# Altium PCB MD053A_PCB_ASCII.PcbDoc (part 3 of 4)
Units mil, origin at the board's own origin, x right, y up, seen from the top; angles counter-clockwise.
Board outline 3650 x 5180 mil, 4 copper layers (Top Layer, GND Layer, Power Layer, Bottom Layer), stack 58.4 mil thick; 251 components, 138 nets, 532 pads, 1017 vias.
Unrouted connection lines stored in the file: 42.
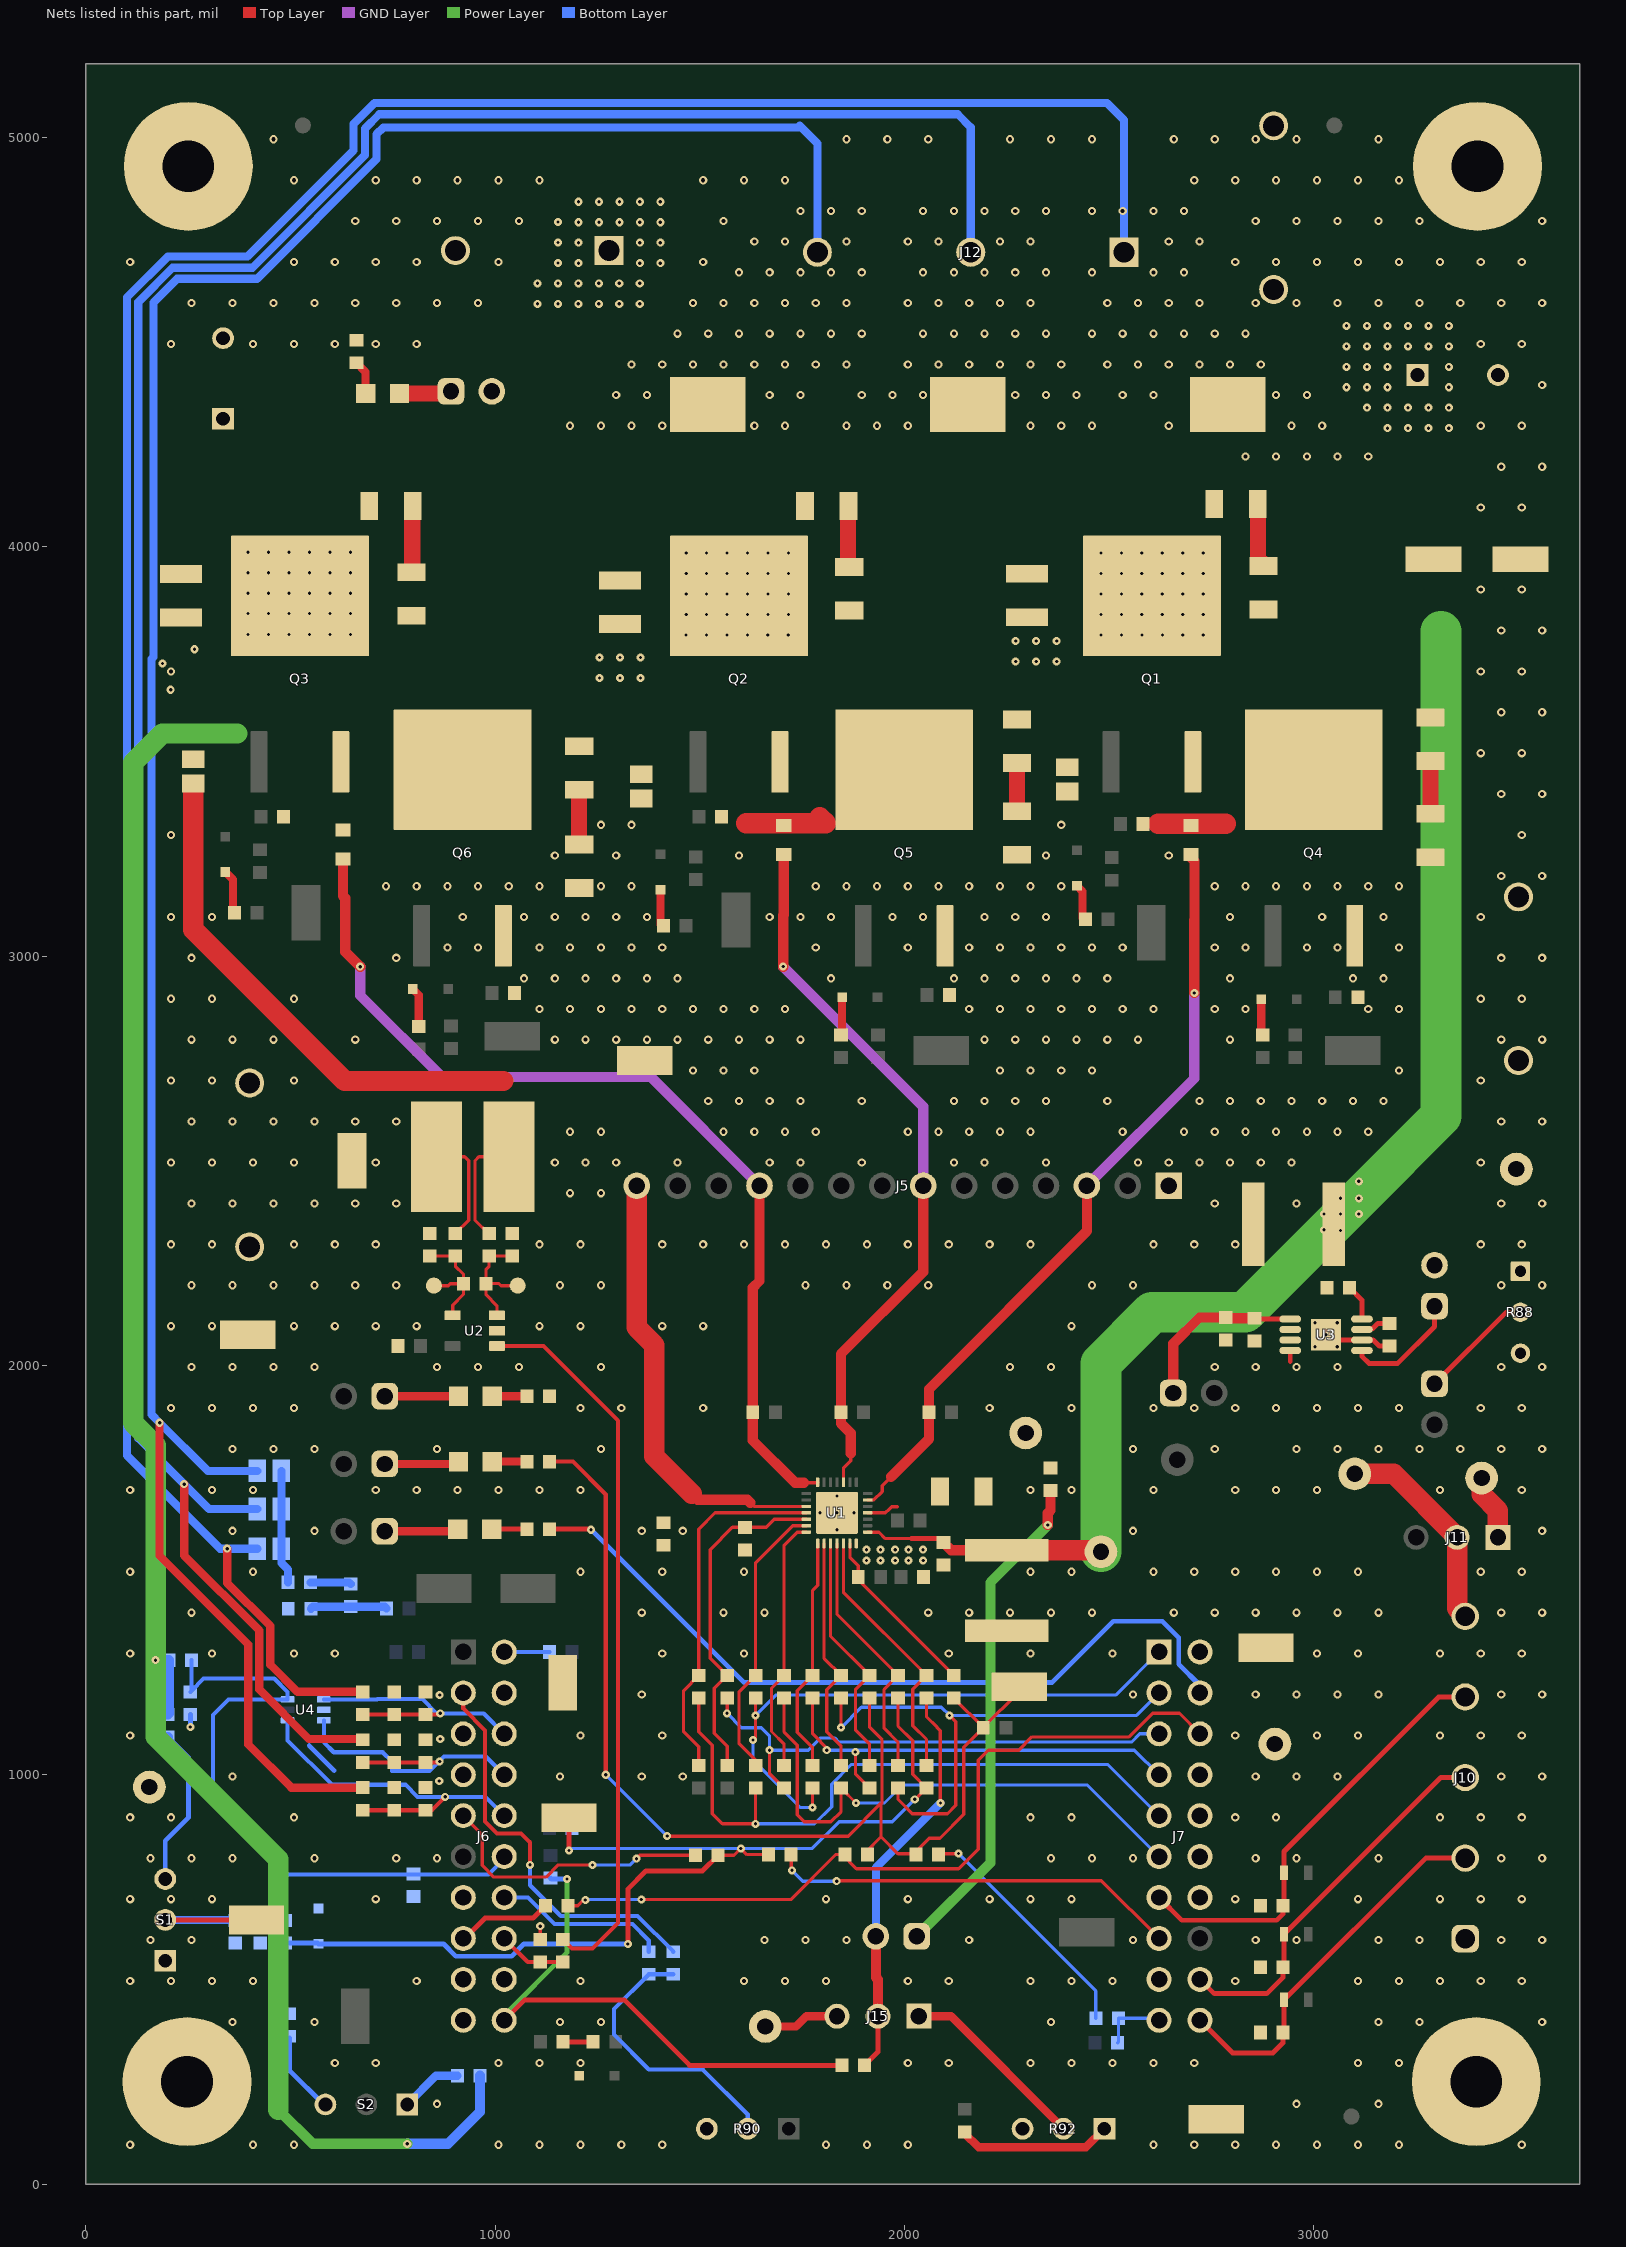
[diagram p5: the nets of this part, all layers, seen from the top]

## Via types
v1: diameter 20, hole 10, Top Layer to Bottom Layer, tented both sides, 759 vias
v2: diameter 19.68, hole 7.87, Top Layer to Bottom Layer, tented both sides, 248 vias
v3: diameter 19.68, hole 7.87, Top Layer to Bottom Layer, 10 vias

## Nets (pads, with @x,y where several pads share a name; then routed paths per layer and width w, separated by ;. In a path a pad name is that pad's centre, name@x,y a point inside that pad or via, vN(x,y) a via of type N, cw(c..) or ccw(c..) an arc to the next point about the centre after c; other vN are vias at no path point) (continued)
GND: C1.1 C2.2 C4.2 C5.2 C7.2 C14.2 C16.2 C18.2 C28.1 C29.2 C31.2 C32.2 C33.2 C34.2 C35.2 C36.2 C37.2 C38.2 C39.2 C40.2 C41.2 C42.2 C43.2 C44.2 C45.1 C46.2 C47.2 C48.2 D11.2 D12.2 J5.1 J6.4 J7.2 J9.2 J10.1 R22.1 R24.1 R60.1 R61.2 R66.1 R70.1 R71.1 R72.1 R77.1 R80.1 R86.1 R88.1 R90.3 R91.1 R92.3 TP5.1 TP6.1 TP7.1 TP9.1 TP10.1 TP22.1 TP25.1 TP25.2 TP26.1 TP26.2 TP27.1 TP27.2 TP28.1 TP29.1 U1.28 U1.29 U2.2 U3.4 U3.6 U3.9 U4.2 | length 616
  Top Layer w7.87: R60.1@856.42,2510 925,2510 935,2500 935,2354.96 R61.2@902.6,2322.56 ; C31.2@1110,597.56 v2(1110,630)
  Top Layer w12: 2942.4,2009.97 U3.4@2942.4,2036.61 ; v3(3030,2075) 3042.8,2062.2 U3.6@3117.6,2062.2 3145.24,2062.2 3160,2047.44 C37.2@3185,2047.44
  Bottom Layer w12: v2(255,1116.81) R66.1@255,1147.44 ; 545.5,1071 606.5,1010
  other v1: 108,96 408,96 508,96 1008,96 1108,96 1208,96 1308,96 1408,96 1808,96 1908,96 2008,96 2608,96 2708,96 2808,96 2908,96 3008,96 3108,96 3208,96 3508,96 858,196 2958,196 3158,196 608,296 708,296 1008,296 1108,296 1208,296 2008,296 2108,296 2308,296 2408,296 2508,296 2608,296 2708,296 3108,296 3208,296 358,396 558,396 1158,396 1258,396 2358,396 3158,396 3258,396 3558,396 108,496 208,496 308,496 408,496 808,496 1208,496 1608,496 1708,496 1808,496 2008,496 2108,496 2308,496 2408,496 2508,496 2808,496 3108,496 3208,496 3308,496 3408,496 3508,496 158,596 258,596 1658,596 1758,596 1858,596 2158,596 2558,596 2858,596 2958,596 3158,596 3258,596 3458,596 3558,596 108,696 208,696 308,696 708,696 1808,696 2008,696 2208,696 2308,696 2408,696 2808,696 3108,696 3308,696 3408,696 3508,696 158,796 258,796 358,796 558,796 758,796 858,796 2358,796 2458,796 2558,796 2858,796 2958,796 3158,796 3458,796 3558,796 108,896 208,896 508,896 2308,896 2408,896 2808,896 2908,896 3308,896 3408,896 3508,896 358,996 1158,996 1358,996 1458,996 2858,996 2958,996 3058,996 3458,996 3558,996 108,1096 1208,1096 1408,1096 2808,1096 3008,1096 3108,1096 3308,1096 3408,1096 3508,1096 1358,1196 2558,1196 2858,1196 2958,1196 3058,1196 3158,1196 3458,1196 3558,1196 108,1296 308,1296 508,1296 608,1296 1408,1296 1608,1296 2108,1296 2308,1296 2508,1296 3008,1296 3108,1296 3308,1296 3408,1296 3508,1296 258,1396 1358,1396 1558,1396 1658,1396 2058,1396 2158,1396 2258,1396 2358,1396 2458,1396 2658,1396 2758,1396 2858,1396 2958,1396 3058,1396 3158,1396 3458,1396 3558,1396 108,1496 408,1496 1208,1496 1408,1496 1608,1496 2308,1496 2408,1496 2608,1496 2708,1496 2808,1496 2908,1496 3008,1496 3108,1496 3408,1496 3508,1496 358,1596 558,1596 1358,1596 1458,1596 2558,1596 3558,1596 108,1696 308,1696 408,1696 708,1696 808,1696 908,1696 1008,1696 1108,1696 1208,1696 2308,1696 2408,1696 2608,1696 2808,1696 2908,1696 3008,1696 3308,1696 3508,1696 358,1796 458,1796 558,1796 858,1796 1258,1796 2558,1796 2758,1796 2958,1796 3058,1796 3158,1796 3258,1796 3358,1796 3458,1796 3558,1796 208,1896 308,1896 408,1896 508,1896 1208,1896 1308,1896 1508,1896 2208,1896 2408,1896 2608,1896 2708,1896 2808,1896 2908,1896 3008,1896 3108,1896 3208,1896 3408,1896 3508,1896 258,1996 358,1996 458,1996 558,1996 858,1996 958,1996 1058,1996 1258,1996 2258,1996 2358,1996 2758,1996 2858,1996 2958,1996 3058,1996 3458,1996 3558,1996 208,2096 308,2096 508,2096 608,2096 708,2096 808,2096 1108,2096 1208,2096 1408,2096 1508,2096 2408,2096 258,2196 358,2196 458,2196 558,2196 658,2196 758,2196 1158,2196 1258,2196 1758,2196 1858,2196 1958,2196 2058,2196 2458,2196 2558,2196 3458,2196 3558,2196 208,2296 308,2296 508,2296 608,2296 708,2296 1108,2296 1208,2296 1408,2296 1508,2296 1608,2296 1708,2296 1808,2296 1908,2296 2008,2296 2108,2296 2208,2296 2308,2296 2608,2296 2708,2296 2808,2296 3408,2296 3508,2296 258,2396 358,2396 458,2396 558,2396 658,2396 758,2396 2758,2396 2958,2396 3458,2396 3558,2396 208,2496 308,2496 408,2496 508,2496 708,2496 3408,2496 258,2596 358,2596 458,2596 558,2596 658,2596 758,2596 3458,2596 3558,2596 208,2696 308,2696 508,2696 3408,2696 258,2796 358,2796 458,2796 658,2796 3458,2796 3558,2796 208,2896 308,2896 508,2896 3408,2896 3508,2896 258,2996 758,2996 3458,2996 3558,2996 208,3096 308,3096 3408,3096 3458,3196 3558,3196 208,3296 3508,3296 3458,3396 3558,3396 3408,3496 3508,3496 3458,3596 3558,3596 208,3696 3408,3696 3508,3696 3458,3796 3558,3796 3408,3896 3508,3896 3408,4096 3508,4096 3458,4196 3558,4196 3408,4296 3508,4296 3558,4396 208,4496 408,4496 508,4496 608,4496 708,4496 808,4496 3408,4496 3508,4496 258,4596 358,4596 458,4596 558,4596 658,4596 758,4596 858,4596 958,4596 2858,4596 2958,4596 3058,4596 3158,4596 3258,4596 3358,4596 3458,4596 3558,4596 108,4696 508,4696 608,4696 708,4696 808,4696 1008,4696 1508,4696 2808,4696 2908,4696 3008,4696 3108,4696 3208,4696 3308,4696 3408,4696 3508,4696 658,4796 758,4796 858,4796 958,4796 1058,4796 1558,4796 2858,4796 2958,4796 3058,4796 3158,4796 3258,4796 3558,4796 508,4896 708,4896 808,4896 908,4896 1008,4896 1108,4896 1508,4896 1608,4896 1708,4896 2708,4896 2808,4896 2908,4896 3008,4896 3108,4896 3208,4896 458,4996 1858,4996 1958,4996 2058,4996 2258,4996 2358,4996 2458,4996 2658,4996 2758,4996 2858,4996 2958,4996 3158,4996
  other v2: 863.15,985 865.54,1087.56 864.2,1195 1907.06,1523.58 1941.09,1523.58 1977.08,1523.58 2010,1523.58 2045.5,1523.58 1907.06,1550 1941.09,1550 1977.08,1550 2010,1550 2045,1550 207,3651 1255,3680 1305,3680 1355,3680 187,3715 2271.66,3720 2321.66,3720 2371.66,3720 1255,3730 1305,3730 1355,3730 265,3750 2271.66,3770 2321.66,3770 2371.66,3770
  other v3: 1835,1598.66 1793.66,1640 1835,1640 1876.34,1640 1835,1681.34 3002.83,2045.87 3057.17,2045.87 3002.83,2104.13 3057.17,2104.13
GVDD: C7.1 R87.1 TP12.1 U1.4 | length 79
  Top Layer w7.87: U1.4@1909.8,1640 1953.18,1640 1962.16,1648.98 1962.69,1648.98 1968.71,1655 1982.54,1655
HALL_PWR: J10.5 J11.2 TP21.1 | length 515.6
  Top Layer w50: TP21.1@3100,1735 3195,1735 J11.2@3350,1580 3350,1406.85 J10.5@3370,1386.85
HALLA: C42.1 J7.13 J10.4 R62.1 | length 1085.1
  Top Layer w12: J7.13@2621.85,700 2677.46,644.39 2909.39,644.39 2924.41,659.41 C42.1@2924.41,680 2927.32,682.91 R62.1@2927.32,760 2927.32,812.32 3305,1190 J10.4@3370,1190
HALLB: C43.1 J7.18 J10.3 R63.1 | length 941.6
  Top Layer w12: J7.18@2721.85,500 2756.85,465 2885,465 2924.41,504.41 C43.1@2924.41,530 2927.32,532.91 R63.1@2927.32,610 3310.47,993.15 J10.3@3370,993.15
HALLC: C44.1 J7.20 J10.2 R64.1 | length 938.7
  Top Layer w12: J7.20@2721.85,400 2801.85,320 2900,320 2924.41,344.41 C44.1@2924.41,370 2927.32,372.91 R64.1@2927.32,450 3273.62,796.3 J10.2@3370,796.3
INHA: J7.1 R5.1 R12.1 | length 1445.3
  Top Layer w7.87: v2(1775.29,920) R5.1@1775.29,967.44
  Top Layer w8: v2(1630,1085) 1636.11,1091.11 v2(1636.11,1145) R12.1@1636.11,1187.44
  Bottom Layer w7.87: v2(1636.11,1145) 1686.11,1195 2516.85,1195 J7.1@2621.85,1300
  Bottom Layer w8: v2(1630,1085) 1630,1035 1745,920 v2(1775.29,920)
INHB: J7.5 R7.1 R14.1 | length 1282.8
  Top Layer w8: v2(1566.52,1150) R14.1@1566.52,1187.44 ; v2(1670,1060) 1670,1003.14 R7.1@1705.7,967.44
  Bottom Layer w8: v2(1566.52,1150) 1601.52,1115 1650,1115 1670,1095 v2(1670,1060) 1765,1060 1795,1090 1829.17,1090 1839.17,1080 2555,1080 2575,1100 J7.5@2621.85,1100
INHC: J7.9 R2.1 R17.1 | length 1629.8
  Top Layer w7.87: 1530,905 1555,880 v2(1636.11,880) R2.1@1636.11,967.44
  Top Layer w8: R17.1@1496.93,1187.44 1496.93,1105 1530,1071.93 1530,905
  Bottom Layer w7.87: v2(1636.11,880) 1780,880 1821.93,921.93 1821.93,976.93 1870,1025 2496.85,1025 J7.9@2621.85,900
INLA: J7.3 R1.1 R13.1 | length 1318.4
  Top Layer w8: v2(1844.88,1115.12) R13.1@1844.88,1187.44 ; R1.1@1984.06,967.44 1984.06,940 2019.06,905 2105,905 2125,925 2125,1130 v2(2110,1145)
  Bottom Layer w8: v2(1844.88,1115.12) 1894.75,1165 2090,1165 v2(2110,1145) 2566.85,1145 J7.3@2621.85,1200
INLB: J7.7 R8.1 R15.1 | length 1096.7
  Top Layer w8: R15.1@1775.29,1187.44 1775.29,1099.71 1815,1060 v2(1810,1060) ; v2(1879.67,1055.42) v2@1880,1055.09 ; v2@1880,1060 v2@1880,1055.09 ; R8.1@1914.47,967.44 1880,1001.91 v2@1880,1055.09
  Bottom Layer w8: v2(1810,1060) 1875.09,1060 v2(1879.67,1055.42) 1884.25,1060 2561.85,1060 J7.7@2621.85,1000
INLC: J7.11 R3.1 R18.1 | length 1363.4
  Top Layer w7.87: R18.1@1705.7,1187.44 1705.7,1104.3 1737.76,1072.24 1737.76,902.24 1755,885 1820,885 1844.88,909.88 R3.1@1844.88,967.44 v2(1881.34,930.98)
  Bottom Layer w7.87: v2(1881.34,930.98) 1950.98,930.98 1995,975 2446.85,975 J7.11@2621.85,800
ISENA: C31.1 J6.16 R59.1 | length 167
  Top Layer w10: J6.16@1021.85,600 1079.41,542.44 C31.1@1110,542.44 R59.1@1165,542.44
LSS: C19.2 C20.2 C21.2 C25.2 C26.2 C27.2 J5.14 Q4.3 Q5.3 Q6.3 R55.1 R56.1 R57.1 R58.2 R60.2 TP3.1 U1.17 | length 2649.2
  Top Layer w7.87: R58.2@995,2322.56 R58.2@985,2322.56 982.44,2322.56 950.75,2354.25 950.75,2500.75 960,2510 R60.2@1033.58,2510 ; 1623.17,1664.86 1632.28,1655.75 U1.17@1760.2,1655.75
  Top Layer w25: 1480,1686.92 1494.92,1672 1616.03,1672 1623.17,1664.86
  Top Layer w50: C21.2@261.85,3411.65 261.85,3065.15 631.94,2695.06 1020,2695.06 ; J5.14@1345.67,2438.91 1345.67,2092.85 1388.52,2050 1388.52,1778.4 1480,1686.92
  other v1: 1183,2421 1258,2421 1145.5,2496 1220.5,2496 1295.5,2496 1445.5,2496 1670.5,2496 1745.5,2496 1895.5,2496 2120.5,2496 2195.5,2496 2345.5,2496 2570.5,2496 2645.5,2496 2720.5,2496 2795.5,2496 2870.5,2496 2945.5,2496 1183,2571 1258,2571 1558,2571 1633,2571 1708,2571 1783,2571 2008,2571 2083,2571 2158,2571 2233,2571 2308,2571 2533,2571 2683,2571 2758,2571 2833,2571 2908,2571 2983,2571 3058,2571 3133,2571 1520.5,2646 1595.5,2646 1670.5,2646 1745.5,2646 1895.5,2646 2120.5,2646 2195.5,2646 2270.5,2646 2345.5,2646 2495.5,2646 2720.5,2646 2795.5,2646 2870.5,2646 2945.5,2646 3020.5,2646 3095.5,2646 3170.5,2646 1483,2721 1558,2721 1633,2721 2233,2721 2308,2721 2383,2721 2458,2721 3208,2721 1145.5,2796 1220.5,2796 1295.5,2796 1370.5,2796 1445.5,2796 1520.5,2796 1595.5,2796 1670.5,2796 1745.5,2796 2195.5,2796 2270.5,2796 2345.5,2796 2420.5,2796 2495.5,2796 2570.5,2796 2795.5,2796 1108,2871 1183,2871 1258,2871 1333,2871 1408,2871 1483,2871 1558,2871 1633,2871 1708,2871 2158,2871 2233,2871 2308,2871 2383,2871 2458,2871 2533,2871 2608,2871 2758,2871 2833,2871 3133,2871 3208,2871 1070.5,2946 1145.5,2946 1220.5,2946 1295.5,2946 1370.5,2946 1445.5,2946 1820.5,2946 2120.5,2946 2195.5,2946 2270.5,2946 2345.5,2946 2420.5,2946 2495.5,2946 2795.5,2946 3095.5,2946 3170.5,2946 883,3021 958,3021 1108,3021 1183,3021 1258,3021 1333,3021 1408,3021 1783,3021 2008,3021 2158,3021 2233,3021 2308,3021 2383,3021 2458,3021 2533,3021 2758,3021 2833,3021 2983,3021 3058,3021 3208,3021 920.5,3096 1070.5,3096 1145.5,3096 1220.5,3096 1295.5,3096 1370.5,3096 1670.5,3096 1745.5,3096 1820.5,3096 1970.5,3096 2045.5,3096 2195.5,3096 2270.5,3096 2345.5,3096 2795.5,3096 3020.5,3096 3170.5,3096 733,3171 808,3171 883,3171 958,3171 1033,3171 1108,3171 1258,3171 1333,3171 1783,3171 1858,3171 1933,3171 2008,3171 2083,3171 2158,3171 2233,3171 2308,3171 2383,3171 2758,3171 2833,3171 2908,3171 2983,3171 3058,3171 3133,3171 3208,3171 1145.5,3246 1295.5,3246 1595.5,3246 2345.5,3246 2645.5,3246 1258,3321 1333,3321 2383,3321
MCU_LED: J7.4 R25.1 | length 1927.9
  Top Layer w12: R25.1@1132.56,1600 1232.44,1600 v2(1233.78,1598.66)
  Bottom Layer w12: v2(1233.78,1598.66) 1235,1598.66 1608.66,1225 2360,1225 2510,1375 2630,1375 2670,1335 2670,1270 2721.85,1218.15 J7.4@2721.85,1200
NC_MCU/POT_49C: J6.14 R39.2 | length 424.1
  Bottom Layer w10: J6.14@1021.85,700 1080,700 1145,635 1335,635 1375,595 R39.2@1375,567.56
NetC2_1: C2.1 C35.1 J16.1 U3.1 | length 434.5
  Top Layer w12: C35.1@2855,2115.35 2856.97,2113.39 U3.1@2942.4,2113.39
  Top Layer w25: J16.1@2656.37,1932.76 2656.37,2053.01 2720.69,2117.32 C2.1@2785,2117.32 2786.97,2115.35 C35.1@2855,2115.35
NetC10_2: C10.2 R40.2 | length 152.4
  Top Layer w39.37: R40.2@2863.43,4103.85 2863.43,3970.75 C10.2@2877.09,3957.09
NetC11_2: C11.2 R41.2 | length 146.2
  Top Layer w39.37: R41.2@1862.09,4100 1862.09,3957.91 C11.2@1865,3955
NetC12_2: C12.2 R42.2 | length 158.8
  Top Layer w39.37: C12.2@795,3942.09 797.09,3944.17 R42.2@797.09,4100
NetC22_2: C22.2 R56.2 | length 109.9
  Top Layer w39.37: R56.2@2275,3357.97 C22.2@2275,3467.91
NetC23_2: C23.2 R57.2 | length 125.8
  Top Layer w39.37: R57.2@1205,3277.09 C23.2@1205,3402.91
NetC24_2: C24.2 R55.2 | length 120.8
  Top Layer w39.37: R55.2@3285,3352.09 C24.2@3285,3472.91
NetC37_1: C37.1 U3.7 | length 73.5
  Top Layer w12: U3.7@3117.6,2087.8 3120.46,2090.65 3144.73,2090.65 3156.64,2102.56 C37.1@3185,2102.56
NetC49_1: C49.1
NetC49_2: C49.2
NetD1_1: D1.1 J1.1 | length 180
  Top Layer w20: J1.1@730,1925 D1.1@910,1925
NetD1_2: D1.2 R22.2 | length 84.8
  Top Layer w20: D1.2@992.68,1925 R22.2@1077.44,1925
NetD2_1: D2.1 J2.1 | length 182.3
  Top Layer w20: J2.1@730,1759.41 904.41,1759.41 D2.1@910,1765
NetD2_2: D2.2 R23.2 | length 84.8
  Top Layer w20: D2.2@992.68,1765 R23.2@1077.44,1765
NetD3_1: D3.1 J3.1 | length 130.2
  Top Layer w39.37: D3.1@763.62,4375 886.77,4375 J3.1@891.77,4380
NetD3_2: D3.2 R24.2 | length 84.1
  Top Layer w19.68: R24.2@661,4449.88 683.31,4427.58 D3.2@683.31,4375
NetD4_1: D4.1 J4.1 | length 180.7
  Top Layer w20: J4.1@730,1595 903.66,1595 D4.1@908.66,1600
NetD4_2: D4.2 R25.2 | length 86.1
  Top Layer w12: D4.2@991.34,1600 R25.2@1077.44,1600
NetD5_1: D5.1 R46.2 | length 84.2
  Top Layer w20: D5.1@2421.3,3172.13 2435.08,3158.35 R46.2@2435.08,3093.66
NetD6_1: D6.1 R47.2 | length 89.6
  Top Layer w20: D6.1@1403.58,3162.28 1403.58,3077.5 R47.2@1406.95,3074.13
NetD7_1: D7.1 R48.2 | length 106.8
  Top Layer w20: D7.1@340.59,3205.59 358.93,3187.25 R48.2@358.93,3106.39
NetD8_1: D8.1 R52.2 | length 84.9
  Top Layer w20: D8.1@2871.69,2895 2871.69,2814.8 R52.2@2875,2811.5
NetD9_1: D9.1 R53.2 | length 91
  Top Layer w20: R53.2@1845,2810 1847.49,2812.49 D9.1@1847.49,2900
NetD10_1: D10.1 R54.2 | length 93.3
  Top Layer w20: D10.1@798.27,2919.83 813.03,2905.07 R54.2@813.03,2832.62
NetH1_1: H1.1
NetH2_1: H2.1
NetH3_1: H3.1
NetH4_1: H4.1
NetJ6_2: J6.2 R30.1 | length 110.6
  Bottom Layer w10: J6.2@1021.85,1300 R30.1@1132.44,1300
NetJ6_5: J6.5
NetJ6_7: J6.7
NetJ6_13: J6.13
NetJ6_15: J6.15 R35.2 | length 233.7
  Top Layer w12: J6.15@921.85,600 925.24,600 975.24,650 1092.44,650 R35.2@1122.44,680
NetJ6_17: J6.17
NetJ6_18: J6.18
NetJ6_19: J6.19
NetJ7_8: J7.8
NetJ7_10: J7.10
NetJ7_12: J7.12
NetJ7_14: J7.14
NetJ7_17: J7.17
NetJ8_1: J8.1 U3.5 | length 286.1
  Top Layer w12: U3.5@3117.6,2036.61 3117.6,2022.4 3135,2005 3205,2005 3295,2095 J8.1@3295,2145
NetJ11_1: J11.1 TP31.1 | length 161.6
  Top Layer w50: TP31.1@3410,1725 3410,1685 3450,1645 J11.1@3450,1580
NetJ13_1: J13.1 R87.2 | length 1224.7
  Top Layer w25: v2(2350,1610) 2350,1638.64 2356.76,1645.4 R87.2@2356.76,1694.35
  Power Layer w25: J13.1@2030,605 2210,785 2210,1470 v2(2350,1610)
NetJ14_1: J14.1 R88.2 | length 282.3
  Top Layer w12: J14.1@3295,1955 3470,2130 R88.2@3504.8,2130
NetJ15_1: J15.1 R92.2 | length 467.3
  Top Layer w20: J15.1@2035,410 2113.35,410 R92.2@2388.35,135
NetJ15_3: J15.3 TP30.1 | length 185.4
  Top Layer w20: TP30.1@1660,385 1735.2,385 1760.2,410 J15.3@1835,410
NetR37_2: R37.2 R76.2 | length 73.4
  Top Layer w12: R76.2@1165.83,347.4 R37.2@1239.25,347.4
NetR73_1: R73.1 S1.3 | length 393.6
  Bottom Layer w12: S1.3@193.7,745.28 193.7,838.7 250,895 250,1042.44 R73.1@200,1092.44
  Bottom Layer w25: R73.1@200,1090 R73.1@200,1092.44
NetR74_1: R74.1 S2.1 | length 151.6
  Bottom Layer w20: S2.1@785,194.37 855.34,264.71 R74.1@907.44,264.71
NetR78_2: R78.2 R81.1 R82.2 R84.2 | length 279
  Bottom Layer w20: R84.2@477.38,1742.3 R82.2@477.38,1649.36 R78.2@477.38,1552.3 477.38,1517.62 493.58,1501.42 R81.1@493.58,1470
NetR80_2: R80.2 S2.3 | length 201.7
  Bottom Layer w12: R80.2@496.85,357.01 496.85,278.15 580.63,194.37 S2.3@585,194.37
NetR81_2: R81.2 R83.2 | length 99.9
  Bottom Layer w20: R81.2@548.7,1470 642.65,1470 R83.2@646.85,1465.8
NetR83_1: R83.1 R85.1 R86.2 | length 188.7
  Bottom Layer w20: R86.2@549.41,1405.72 554.36,1410.68 R83.1@646.85,1410.68 729.93,1410.68 R85.1@734.29,1406.31
NetR88_3: R88.3
NetR89_1: R89.1 R92.1 | length 374.1
  Top Layer w20: R89.1@2146.85,123.5 2180.4,89.95 2443.3,89.95 R92.1@2488.35,135
NetS1_1: S1.1
NetU1_20: 
NetU1_21: 
NetU1_22: 
NetU3_2: U3.2
NetU3_3: U3.3
nFAULT: R9.1 R16.2 R19.1 R23.1 R31.1 R33.1 TP4.1 | length 2765.5
  Top Layer w8: v2(1420,850) 1862.44,850 1942.44,930 ; R33.1@1905.11,810.58 1942.44,847.9 ; R19.1@1914.47,1187.44 1914.47,1115.53 1945,1085 1945,930 1942.44,930 ; R31.1@2027.69,805.11 2025.54,807.26 R31.1@2022.44,807.26 ; R9.1@2120.5,1187.44 R16.2@2192.44,1115.5 ; TP4.1@2280,1215 2280,1203.06 R16.2@2192.44,1115.5 ; 1942.44,847.9 1943.32,847.9 1983.97,807.26 R31.1@2022.44,807.26 ; 1942.44,847.9 1942.44,930 ; R31.1@2022.44,807.26 2060.18,845 2086.68,845 2145,903.32 2145,1067.56 R16.2@2192.44,1115 R16.2@2192.44,1115.5
  Top Layer w10: R23.1@1132.56,1765 1190,1765 1270,1685 v2(1270,1000)
  Bottom Layer w8: v2(1270,1000) v2(1420,850)
nFAULT_49C: R31.2 R38.1 | length 595.6
  Top Layer w8: R31.2@2077.56,807.26 v2(2131.95,807.26)
  Bottom Layer w8: v2(2131.95,807.26) 2467.44,471.76 R38.1@2467.44,405
nFAULT_49C/CSAREF: J7.19 R36.2 R38.2 | length 162.1
  Bottom Layer w8: R36.2@2520.83,345 2522.56,346.73 R38.2@2522.56,405 2616.85,405 J7.19@2621.85,400
nFAULT_DFLT: J7.6 R33.2 R35.1 | length 1923.5
  Top Layer w8: R35.1@1177.56,680 1201.47,680 1215.59,694.12 v2(1220,694.12) ; v2(1356.8,695) 1721.88,695 1831.98,805.11 R33.2@1847.34,805.11 ; R33.2@1854.26,805.11 R33.2@1847.34,805.11 ; J7.6@2721.85,1100 2671.85,1150 2606.26,1150 2548.7,1092.44 2311.2,1092.44 2278.76,1060 2204.58,1060 2180,1035.42 2180,818.07 2131.93,770 1882.45,770 R33.2@1847.34,805.11
  Bottom Layer w8: v2(1220,694.12) 1220,695 v2(1356.8,695)
nSLEEP: D11.1 R10.1 R11.1 R26.1 R27.1 R75.2 TP2.1 | length 2654
  Top Layer w7.87: R27.1@1544.49,803.25 1583.25,803.25 v2(1600,820) 1615,805 R26.1@1667.95,805 ; R11.1@1984.06,1187.44 1984.06,1118.94 2020,1083 2020,1001.09 R10.1@2053.65,967.44 2026.2,940 v2(2025,940)
  Top Layer w12: v2(1180,815) TP2.1@1180,895 ; v2(1323.85,586.53) 1323.85,720.63 1368.22,765 1506.24,765 R27.1@1544.49,803.25
  Bottom Layer w7.87: 1345,820 v2(1600,820) 1775,820 1840,885 1970,885 v2(2025,940)
  Bottom Layer w8: v2(1180,815) 1185,820 1345,820
  Bottom Layer w12: R75.2@486.85,588.66 566.22,588.66 D11.1@568.19,586.69 873.62,586.69 903.83,556.49 1039.87,556.49 1069.92,586.53 v2(1323.85,586.53)
nSLEEP_49C: J7.15 R26.2 | length 1005.9
  Top Layer w8: R26.2@1723.07,805 1723.07,768.34 v2(1725,766.41) ; v2(1834.14,740) 1835,740.86 2480.99,740.86 J7.15@2621.85,600
  Bottom Layer w8: v2(1725,766.41) 1751.41,740 v2(1834.14,740)
nSLEEP_DFLT: J6.9 R27.2 | length 710.3
  Top Layer w7.87: J6.9@907.44,900 J6.9@921.85,900 967.97,853.88 967.97,778.45 996.41,750 1124.29,750 1153.86,779.57 v2(1237.4,779.57) ; v2(1345,795) 1353.25,803.25 R27.2@1489.37,803.25
  Bottom Layer w7.87: v2(1237.4,779.57) 1329.57,779.57 v2(1345,795)
nSLEEP_SW: C36.1 R75.1 R77.2 S1.2 TP23.1 | length 517
  Top Layer w12: S1.2@193.7,645.28 416.57,645.28 TP23.1@416.85,645
  Bottom Layer w12: R75.1@485.36,645.28 R75.1@486.85,643.78
  Bottom Layer w20: S1.2@193.7,645.28 R75.1@485.36,645.28
OUTA: C10.1 C13.2 C24.1 J12.1 NT1.2 Q1.3 Q4.4 R67.2 R78.1 TP34.1 | length 7000.1
  Top Layer w20: v2(345,1552.3) 345,1468.88 450.43,1363.44 450.43,1268.69 516.57,1202.56 R67.2@676.39,1202.56
  Top Layer w50: 2619.68,3323.5 2700,3323.5 2784.46,3323.5
  Bottom Layer w20: R78.1@418.32,1552.3 v2(345,1552.3) 327.7,1552.3 100,1780 100,4610 200,4710 395,4710 653.78,4968.78 653.78,5033.78 705,5085 2495,5085 2536.61,5043.39 J12.1@2536.61,4720
  other v1: 2833,4221 2908,4221 2983,4221 3058,4221 3133,4221 2645.5,4296 2945.5,4296 3020.5,4296 2533,4371 2608,4371 2908,4371 2983,4371 2495.5,4446 2570.5,4446 2645.5,4446 2720.5,4446 2795.5,4446 2870.5,4446 2458,4521 2533,4521 2608,4521 2683,4521 2758,4521 2833,4521 2495.5,4596 2570.5,4596 2645.5,4596 2720.5,4596 2458,4671 2608,4671 2683,4671 2645.5,4746 2720.5,4746 2458,4821 2533,4821 2608,4821 2683,4821
OUTB: C11.1 C15.2 C22.1 J12.2 NT2.2 Q2.3 Q5.4 R68.2 R82.1 TP35.1 | length 6817
  Top Layer w20: v2(240,1710) 240,1535.69 423.43,1352.26 423.43,1208.38 544.25,1087.56 674.32,1087.56 R68.2@676.39,1085.49 ; NT2.2@1704.76,3324.33 NT2.2@1715.47,3324.33
  Top Layer w50: 1613.18,3324.33 NT2.2@1704.76,3324.33 ; NT2.2@1715.47,3324.33 1808.12,3324.33 1792.75,3339.7
  Bottom Layer w20: R82.1@418.32,1649.36 300.64,1649.36 v2(240,1710) 127.87,1822.13 127.87,4598.45 211.55,4682.13 406.55,4682.13 681.65,4957.23 681.65,5022.23 716.55,5057.13 2130,5057.13 2161.8,5025.32 J12.2@2161.8,4720
  other v1: 1858,4296 1933,4296 2008,4296 2308,4296 2383,4296 2458,4296 1895.5,4371 1970.5,4371 2045.5,4371 2270.5,4371 2345.5,4371 2420.5,4371 2008,4446 2083,4446 2158,4446 2233,4446 2308,4446 2383,4446 2045.5,4521 2120.5,4521 2195.5,4521 2270.5,4521 2345.5,4521 2008,4596 2083,4596 2158,4596 2233,4596 2308,4596 2045.5,4671 2120.5,4671 2195.5,4671 2270.5,4671 2345.5,4671 2008,4746 2083,4746 2233,4746 2308,4746 2045.5,4821 2120.5,4821 2195.5,4821 2270.5,4821 2345.5,4821
OUTC: C12.1 C17.2 C23.1 J12.3 NT3.2 Q3.3 Q6.4 R69.2 R84.1 TP36.1 | length 6354.6
  Top Layer w20: v2(180,1860) 180,1535 396.43,1318.57 396.43,1073.75 501.76,968.42 R69.2@676.39,968.42
  Bottom Layer w20: R84.1@418.32,1742.3 297.7,1742.3 v2(180,1860) 160.16,1879.84 160.16,3726.12 165,3730.96 165,4597.4 222.73,4655.13 417.73,4655.13 710,4947.4 710,5008.45 726.55,5025 1740.09,5025 1744.09,5029 1787,4986.09 J12.3@1787,4720
  other v1: 1183,4296 1258,4296 1333,4296 1408,4296 1633,4296 1708,4296 1295.5,4371 1370.5,4371 1670.5,4371 1745.5,4371 1333,4446 1408,4446 1483,4446 1558,4446 1633,4446 1708,4446 1783,4446 1858,4446 1445.5,4521 1520.5,4521 1595.5,4521 1670.5,4521 1745.5,4521 1820.5,4521 1895.5,4521 1483,4596 1558,4596 1633,4596 1708,4596 1783,4596 1858,4596 1595.5,4671 1670.5,4671 1745.5,4671 1820.5,4671 1895.5,4671 1633,4746 1708,4746 1858,4746 1745.5,4821 1820.5,4821 1895.5,4821
P18: R6.2 R17.2 U1.18 | length 887.9
  Top Layer w8: R6.2@1496.93,1022.56 1496.93,1068.07 1460,1105 1460,1205.63 R17.2@1496.93,1242.56 1496.93,1600 1536.93,1640 U1.18@1760.2,1640
P19: C1.2 R4.2 R14.2 U1.19 | length 836.7
  Top Layer w8: R4.2@1566.52,1022.56 1566.52,1069.48 1535,1101 1535,1211.04 R14.2@1566.52,1242.56 1525,1284.08 1525,1550 1579.57,1604.57 C1.2@1610,1604.57 1662.13,1604.57 1681.81,1624.25 U1.19@1760.2,1624.25
P20: R2.2 R12.2 U1.20 | length 690.7
  Top Layer w8: R2.2@1636.11,1022.56 1636.11,1035.82 1595.5,1076.43 1595.5,1201.95 R12.2@1636.11,1242.56 1636.11,1518.12 1726.5,1608.5 U1.20@1760.2,1608.5
P21: R7.2 R18.2 U1.21 | length 631.3
  Top Layer w8: R7.2@1705.7,1022.56 1705.7,1049.29 1705.63,1049.36 1705.63,1075.06 1675,1105.7 1675,1211.86 R18.2@1705.7,1242.56 1705.7,1560.7 1737.76,1592.76 U1.21@1760.2,1592.76
P22: R5.2 R15.2 U1.22 | length 578.9
  Top Layer w8: R5.2@1775.29,1022.56 1775.29,1066.21 1737.76,1103.74 1737.76,1205.03 R15.2@1775.29,1242.56 1775.29,1450.29 1787.76,1462.76 U1.22@1787.76,1565.2
P23: R3.2 R13.2 U1.23 | length 588.7
  Top Layer w8: U1.23@1803.5,1565.2 1803.5,1283.93 R13.2@1844.88,1242.56 1810,1207.68 1810,1105 1844.88,1070.12 R3.2@1844.88,1022.56
P24: R8.2 R19.2 U1.24 | length 610.6
  Top Layer w8: U1.24@1819.25,1565.2 1819.25,1337.77 R19.2@1914.47,1242.56 1880,1208.09 1880,1109.47 1914.47,1075 R8.2@1914.47,1022.56
P25: R1.2 R11.2 U1.25 | length 632.6
  Top Layer w8: U1.25@1835,1565.2 1835,1391.61 R11.2@1984.06,1242.56 1950,1208.5 1950,1113.74 1984.06,1079.68 R1.2@1984.06,1022.56
P26: R10.2 R21.2 U1.26 | length 654.6
  Top Layer w8: U1.26@1850.75,1565.2 1850.75,1445.46 R21.2@2053.65,1242.56 2020,1208.91 2020,1120 2053.65,1086.35 R10.2@2053.65,1022.56
P27: R9.2 R20.2 U1.27 | length 425.8
  Top Layer w8: U1.27@1866.5,1565.2 1866.5,1531.42 1886.91,1511.01 R20.2@1886.91,1483.21 ; R20.2@1883.38,1479.68 R9.2@2120.5,1242.56
POT: R34.1 R39.1 R90.2 | length 685.3
  Bottom Layer w10: R34.1@1435,512.44 R39.1@1375,512.44 1290,427.44 1290,365 1375,280 1506.87,280 1616.93,169.94 R90.2@1616.93,135
POT_MCU/NC_49C: J6.3 R34.2 | length 989.7
  Top Layer w10: J6.3@921.85,1200 921.85,1161.36 975,1108.21 975,885.49 1003.88,856.61 1063.39,856.61 1085,835 v2(1085,780)
  Bottom Layer w10: v2(1085,780) 1085,730 1160,655 1347.56,655 R34.2@1435,567.56
PVDD: C4.1 C5.1 C14.1 C16.1 C18.1 C19.1 C20.1 C21.1 C33.1 C34.1 C38.1 C39.1 C40.1 J3.2 J8.2 J9.1 Q1.4 Q2.4 Q3.4 R40.1 R41.1 R42.1 R65.2 R73.2 R74.2 TP11.1 U1.1 U3.8 | length 7936.5
  Top Layer w7.87: U1.1@1909.8,1592.76 1937.66,1592.76 1953.41,1577.01 2017.27,1577.01
  Top Layer w12: 2017.27,1576.98 2085.58,1576.98 C5.1@2095,1567.56 ; C34.1@3087.56,2190 3117.6,2159.96 U3.8@3117.6,2113.39
  Top Layer w25: C5.1@2095,1567.56 2114.13,1548.43 C4.1@2250,1548.43
  Top Layer w50: C4.1@2250,1548.43 2476.57,1548.43 TP11.1@2480,1545
  Power Layer w25: 470,181.77 553.66,98.11 v2(785,98.11)
  Power Layer w50: v2(170,1280) 170,1093.15 470,793.15 470,181.77 ; v2@170,1285 170,1805 115,1860 115,3473.01 186.12,3544.13 369.85,3544.13
  Power Layer w100: TP11.1@2480,1545 2480,2005 2605,2130 2831.5,2130 v2(3110,2408.5) 3310.96,2609.47 3310.96,3793.98
  Bottom Layer w25: v2(170,1280) R65.2@202.44,1280 202.44,1150 R73.2@200,1147.56 ; v2(785,98.11) 884.66,98.11 962.56,176 R74.2@962.56,264.71
  other v2: 3065,2330 3025,2331.47 3025,2370 3065,2370 3110,2370 3065,2408.5 3110,2450 1466,3785 1516,3785 1566,3785 1616,3785 1666,3785 1716,3785 2480,3785 2530,3785 2580,3785 2630,3785 2680,3785 2730,3785 396,3786 446,3786 496,3786 546,3786 596,3786 646,3786 1466.43,3834.85 1516.43,3834.85 1566.43,3834.85 1616.43,3834.85 1666.43,3834.85 1716.43,3834.85 2479.88,3834.96 2529.88,3834.96 2579.88,3834.96 2629.88,3834.96 2679.88,3834.96 2729.88,3834.96 396.2,3837.09 446.2,3837.09 496.2,3837.09 546.2,3837.09 596.2,3837.09 646.2,3837.09 1466.43,3884.85 1516.43,3884.85 1566.43,3884.85 1616.43,3884.85 1666.43,3884.85 1716.43,3884.85 2479.88,3884.96 2529.88,3884.96 2579.88,3884.96 2629.88,3884.96 2679.88,3884.96 2729.88,3884.96 396.2,3887.09 446.2,3887.09 496.2,3887.09 546.2,3887.09 596.2,3887.09 646.2,3887.09 1466.43,3934.85 1516.43,3934.85 1566.43,3934.85 1616.43,3934.85 1666.43,3934.85 1716.43,3934.85 2479.88,3934.96 2529.88,3934.96 2579.88,3934.96 2629.88,3934.96 2679.88,3934.96 2729.88,3934.96 396.2,3937.09 446.2,3937.09 496.2,3937.09 546.2,3937.09 596.2,3937.09 646.2,3937.09 1466.43,3984.85 1516.43,3984.85 1566.43,3984.85 1616.43,3984.85 1666.43,3984.85 1716.43,3984.85 2479.88,3984.96 2529.88,3984.96 2579.88,3984.96 2629.88,3984.96 2679.88,3984.96 2729.88,3984.96 396.2,3987.09 446.2,3987.09 496.2,3987.09 546.2,3987.09 596.2,3987.09 646.2,3987.09 3180,4290.14 3230,4290.14 3280,4290.14 3330,4290.14 3130,4340.14 3180,4340.14 3230,4340.14 3280,4340.14 3330,4340.14 3080,4390.14 3130,4390.14 3180,4390.14 3330,4390.14 3080,4440.14 3130,4440.14 3180,4440.14 3330,4440.14 3080,4490.14 3130,4490.14 3180,4490.14 3230,4490.14 3280,4490.14 3330,4490.14 3080,4540.14 3130,4540.14 3180,4540.14 3230,4540.14 3280,4540.14 3330,4540.14 1103,4594 1153,4594 1203,4594 1253,4594 1303,4594 1353,4594 1103,4644 1153,4644 1203,4644 1253,4644 1303,4644 1353,4644 1203.24,4693.35 1353.24,4693.35 1403.24,4693.35 1153,4694 1203.24,4743.35 1353.24,4743.35 1403.24,4743.35 1153,4744 1203.24,4793.35 1253.24,4793.35 1303.24,4793.35 1353.24,4793.35 1403.24,4793.35 1153,4794 1203.24,4843.35 1253.24,4843.35 1303.24,4843.35 1353.24,4843.35 1403.24,4843.35
SHA: C3.2 J5.3 NT1.1 U1.6 | length 1912.5
  Top Layer w7.87: U1.6@1909.8,1671.5 1925.23,1671.5 1945.67,1691.94 1945.67,1706.48 1967.1,1727.9
  Top Layer w25: 1967.1,1727.9 2060,1820.8 C3.2@2060,1885.43 2060,1942.63 2445.67,2328.3 J5.3@2445.67,2438.91 ; NT1.1@2700,3240.63 2708.5,3232.13 2708.5,3088.66 2708,3088.16 v2(2708,2910)
  GND Layer w25: J5.3@2445.67,2438.91 2708,2701.24 v2(2708,2910)
SHB: C8.2 J5.7 NT2.1 U1.10 | length 1772.3
  Top Layer w7.87: U1.10@1850.75,1714.8 1850.75,1749.06 1868.46,1766.77 1868.46,1785
  Top Layer w25: v2(1703.5,2974.5) 1703.5,3100 1704.76,3101.26 NT2.1@1704.76,3244.33 ; 1868.46,1785 1868.46,1834.67 1844.6,1858.53 C8.2@1844.6,1885.43 1844.6,2027.9 2045.67,2228.97 J5.7@2045.67,2438.91
  GND Layer w25: v2(1703.5,2974.5) 2045.67,2632.33 J5.7@2045.67,2438.91
SHC: C9.2 J5.11 NT3.1 U1.14 | length 2345
  Top Layer w7.87: 1754.29,1713.33 1786.28,1713.33 U1.14@1787.76,1714.8
  Top Layer w25: NT3.1@627.77,3232.52 627.77,3147.31 633.5,3141.57 633.5,3010.96 v2(670,2974.47) ; C9.2@1629.2,1885 1629.2,1816.79 1732.67,1713.33 1754.29,1713.33 ; C9.2@1629.2,1885.43 1629.2,2190 1645.67,2206.47 J5.11@1645.67,2438.91
  GND Layer w25: v2(670,2974.47) 670,2903.85 868.85,2705 1379.58,2705 J5.11@1645.67,2438.91
SN: C30.2 C32.1 R61.1 TP33.1 U2.4 | length 301.4
  Top Layer w8: C32.1@840,2267.44 R61.1@902.6,2267.44 902.6,2242.4 922.44,2222.56 C30.2@922.44,2200 ; TP33.1@850,2195 885,2195 890,2200 C30.2@922.44,2200 ; U2.4@895.87,2122.4 895.87,2147.2 922.44,2173.78 C30.2@922.44,2200
SOA: R59.2 U2.1 | length 1769.2
  Top Layer w10: U2.1@1004.13,2047.6 1117.4,2047.6 1300,1865 1300,637.6 1237.4,575 1187.56,575 R59.2@1165,597.56
SP: C28.2 C30.1 R58.1 TP32.1 U2.3 | length 294.9
  Top Layer w7.87: U2.3@1004.13,2122.4 1004.13,2145.87 977.56,2172.44 C30.1@977.56,2200 ; C28.2@1041.38,2267.44 R58.1@985,2267.44 985,2242.44 977.56,2235 C30.1@977.56,2200 ; TP32.1@1054.88,2195 1014.18,2195 1009.18,2200 C30.1@977.56,2200
VDSLVL: J13.2 J15.2 R21.1 R28.2 | length 992.4
  Top Layer w8: R21.1@2053.65,1187.44 2053.65,1141.89 2080,1115.53 2080,1115 2087.56,1107.44 v2(2087.56,930.98)
  Top Layer w12: R28.2@1902.31,290 1935,322.69 J15.2@1935,410
  Top Layer w25: J13.2@1930,605 1930,505 1935,500 J15.2@1935,410
  Bottom Layer w20: J13.2@1930,605 1930,773.42 v2(2087.56,930.98)
VDSLVL/C_TAP: J6.20 R28.1 R32.1 | length 1361.8
  Top Layer w12: J6.20@1021.85,400 1071.85,450 1315,450 1475,290 R28.1@1847.19,290
  Power Layer w12: J6.20@1021.85,400 1021.85,411.85 1175,565 v2(1175,745)
  Bottom Layer w12: R32.1@1135,747.44 1137.44,745 v2(1175,745)
VSENA: C45.2 J6.6 R67.1 R70.2 U4.1 | length 666.7
  Top Layer w10: R67.1@676.39,1147.44 R70.2@753.08,1147.44 C45.2@829.77,1147.44 862.98,1147.44 v2(865.54,1150)
  Bottom Layer w10: U4.1@581.14,1184.09 711.74,1184.09 712.65,1185 821.91,1185 856.91,1150 v2@865,1150 ; v2@865,1150.54 v2(865.54,1150) 971.85,1150 J6.6@1021.85,1100
VSENB: C46.1 J6.8 R68.1 R71.2 U4.3 | length 759.5
  Top Layer w10: R68.1@676.39,1030.37 R71.2@753.08,1030.37 C46.1@829.77,1030.37 862.13,1030.37 v2(864.2,1032.44)
  Bottom Layer w10: U4.3@581.14,1132.91 581.14,1079.28 605.42,1055 725,1055 747.41,1032.59 747.41,1009 839,1009 v2@863.32,1033.32 ; v2(864.2,1032.44) v2@866.76,1035 ; v2@865.88,1035.88 875,1045 976.77,1045 1021.77,1000 J6.8@1021.85,1000
VSENC: C47.1 J6.10 R69.1 R72.2 U4.4 | length 869.4
  Top Layer w10: R69.1@676.39,913.3 R72.2@753.08,913.3 C47.1@829.77,913.3 844.93,913.3 v2(877.6,945.97)
  Bottom Layer w10: U4.4@492.56,1132.91 492.56,1083.64 600.59,975.61 780.24,975.61 809.85,946 975.85,946 J6.10@1021.85,900
VSENPVDD: C41.1 J6.12 R65.1 R66.2 U4.6 | length 1576.3
  Bottom Layer w10: R66.2@255,1202.56 R66.2@257.56,1205.12 ; R65.1@257.56,1280 R66.2@257.56,1205.12 ; J6.12@1021.85,800 1021.85,795.08 983.39,756.61 483.39,756.61 310,930 310,1145.52 348.58,1184.09 U4.6@492.56,1184.09 492.56,1202.44 460,1235 287.44,1235 R66.2@257.56,1205.12
pads on no net: FID1.1 FID2.1 FID3.1 H5.0 H6.0 H7.0 H8.0 LBL1.0 SH-J1.0 SH-J2.0 SH-J3.0 SH-J4.0 SH-J5.0 SH-J6.0 SH-J7.0 SH-J8.0 SH-J9.0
